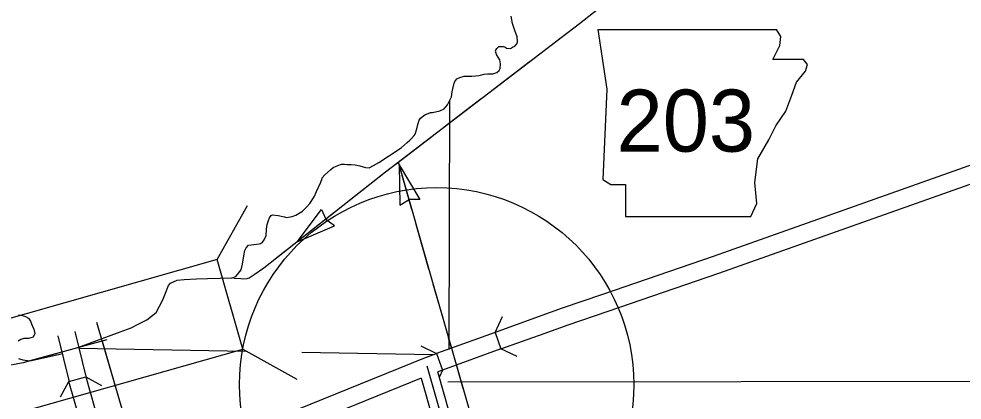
# Model space of a CAD drawing. Extents: x 1373094 to 1376427, y 1168361 to 1170494.
# Drawn here: x 1373442.4 to 1373576.1, y 1170261.2 to 1170315.3 of the extents above; entities that cross this region are included whole.
import ezdxf

# ---------------------------------------------------------------- set-up
doc = ezdxf.new("R2010")
doc.units = 0
doc.layers.add('R_Axis', color=7, linetype='Continuous')
doc.layers.add('R_Draft', color=7, linetype='Continuous')

msp = doc.modelspace()

# ---------------------------------------------------------------- linework, layer by layer
at = {"layer": 'R_Axis'}
for p, q in [((1373524.43, 1170313.73), (1373525.7, 1170305.27)), ((1373550.37, 1170312.74), (1373549.78, 1170313.72)), ((1373550.23, 1170311.47), (1373550.37, 1170312.74)), ((1373549.24, 1170309.5), (1373550.23, 1170311.47)), ((1373553.61, 1170309.5), (1373549.24, 1170309.5)), ((1373554.17, 1170308.79), (1373553.61, 1170309.5)), ((1373552.62, 1170306.26), (1373553.89, 1170307.81)), ((1373553.89, 1170307.81), (1373554.17, 1170308.79)), ((1373551.92, 1170304.42), (1373552.62, 1170306.26)), ((1373525.7, 1170305.27), (1373525.13, 1170292.44)), ((1373551.07, 1170302.17), (1373551.92, 1170304.42)), ((1373549.66, 1170300.05), (1373551.07, 1170302.17)), ((1373548.68, 1170298.08), (1373549.66, 1170300.05)), ((1373547.13, 1170295.4), (1373548.68, 1170298.08)), ((1373496.29, 1170294.55), (1373496.37, 1170288.83)), ((1373496.29, 1170294.55), (1373499.22, 1170289.64)), ((1373546.7, 1170292.02), (1373547.13, 1170295.4)), ((1373525.13, 1170292.44), (1373526.26, 1170291.74)), ((1373526.26, 1170291.74), (1373528.37, 1170291.74)), ((1373528.37, 1170291.74), (1373528.37, 1170287.22)), ((1373546.98, 1170289.06), (1373546.7, 1170292.02)), ((1373496.37, 1170288.83), (1373497.68, 1170289.61)), ((1373499.22, 1170289.64), (1373497.7, 1170289.62)), ((1373546.14, 1170287.22), (1373546.98, 1170289.06)), ((1373470.5, 1170281.1), (1373474.79, 1170288.78)), ((1373481.84, 1170283.63), (1373485.26, 1170288.21)), ((1373485.26, 1170288.21), (1373485.86, 1170286.82)), ((1373487.09, 1170285.89), (1373485.87, 1170286.8)), ((1373528.37, 1170287.22), (1373546.14, 1170287.22)), ((1373481.84, 1170283.63), (1373487.09, 1170285.89)), ((1373474.1, 1170268.4), (1373481.79, 1170264.11)), ((1373501.59, 1170267.78), (1373502.44, 1170265.43))]:
    msp.add_line(p, q, dxfattribs=at)
for points in [[(1373569.11, 1170326.38), (1373530.8, 1170320.46), (1373530.35, 1170320.31), (1373529.83, 1170320.03), (1373529.18, 1170319.74), (1373527.99, 1170319.08), (1373525.82, 1170317.65), (1373521.83, 1170314.55), (1373494.34, 1170293.49), (1373477.11, 1170279.9), (1373475.7, 1170278.91), (1373475.01, 1170278.46), (1373474.69, 1170278.37), (1373474.24, 1170278.33), (1373473.82, 1170278.35), (1373472.85, 1170278.41)], [(1373493.37, 1170294.86), (1373496.58, 1170296.95), (1373497.41, 1170297.69), (1373497.81, 1170298.06), (1373498.04, 1170298.29), (1373498.4, 1170298.7), (1373498.53, 1170298.87), (1373498.79, 1170299.63), (1373498.92, 1170300.27), (1373499.12, 1170300.87), (1373499.31, 1170301.14), (1373499.91, 1170301.64), (1373500.74, 1170301.95), (1373501, 1170301.95), (1373502.03, 1170302.19), (1373502.66, 1170302.49), (1373503.12, 1170303.06), (1373503.68, 1170304.2), (1373503.81, 1170304.9), (1373504.07, 1170306.11), (1373504.16, 1170306.37), (1373504.46, 1170306.74), (1373504.86, 1170306.95), (1373505.49, 1170307.12), (1373505.82, 1170307.12), (1373506.15, 1170307.12), (1373506.59, 1170307.12), (1373507.08, 1170307.16), (1373507.62, 1170307.23), (1373508.31, 1170307.4), (1373508.81, 1170307.47), (1373509.57, 1170307.44), (1373510.11, 1170307.64), (1373510.44, 1170307.91), (1373510.57, 1170308.21), (1373510.66, 1170308.85), (1373510.53, 1170309.45), (1373510.29, 1170309.81), (1373510.05, 1170310.18), (1373510.02, 1170310.41), (1373509.95, 1170310.58), (1373509.99, 1170310.68), (1373509.95, 1170310.81), (1373510.02, 1170310.91), (1373510.12, 1170311.05), (1373510.41, 1170311.32), (1373510.74, 1170311.35), (1373511.08, 1170311.35), (1373511.24, 1170311.26), (1373511.51, 1170311.09), (1373512.04, 1170311.06), (1373512.34, 1170311.23), (1373512.67, 1170311.36), (1373513, 1170311.73), (1373513.03, 1170311.97), (1373513, 1170312.7), (1373512.69, 1170313.6), (1373512.32, 1170314.6), (1373512.15, 1170315.63)], [(1373493.37, 1170294.86), (1373496.58, 1170296.95), (1373497.41, 1170297.69), (1373497.81, 1170298.06), (1373498.04, 1170298.29), (1373498.4, 1170298.7), (1373498.53, 1170298.87), (1373498.79, 1170299.63), (1373498.92, 1170300.27), (1373499.12, 1170300.87), (1373499.31, 1170301.14), (1373499.91, 1170301.64), (1373500.74, 1170301.95), (1373501, 1170301.95), (1373502.03, 1170302.19), (1373502.66, 1170302.49), (1373503.12, 1170303.06), (1373503.68, 1170304.2), (1373503.81, 1170304.9), (1373504.07, 1170306.11), (1373504.16, 1170306.37), (1373504.46, 1170306.74), (1373504.86, 1170306.95), (1373505.49, 1170307.12), (1373505.82, 1170307.12), (1373506.15, 1170307.12), (1373506.59, 1170307.12), (1373507.08, 1170307.16), (1373507.62, 1170307.23), (1373508.31, 1170307.4), (1373508.81, 1170307.47), (1373509.57, 1170307.44), (1373510.11, 1170307.64), (1373510.44, 1170307.91), (1373510.57, 1170308.21), (1373510.66, 1170308.85), (1373510.53, 1170309.45), (1373510.29, 1170309.81), (1373510.05, 1170310.18), (1373510.02, 1170310.41), (1373509.95, 1170310.58), (1373509.99, 1170310.68), (1373509.95, 1170310.81), (1373510.02, 1170310.91), (1373510.12, 1170311.05), (1373510.41, 1170311.32), (1373510.74, 1170311.35), (1373511.08, 1170311.35), (1373511.24, 1170311.26), (1373511.51, 1170311.09), (1373512.04, 1170311.06), (1373512.34, 1170311.23), (1373512.67, 1170311.36), (1373513, 1170311.73), (1373513.03, 1170311.97), (1373513, 1170312.7), (1373512.69, 1170313.6), (1373512.32, 1170314.6), (1373512.15, 1170315.63)], [(1373521.87, 1170314.58), (1373521.83, 1170314.55), (1373519.25, 1170312.57)], [(1373524.43, 1170313.73), (1373549.78, 1170313.72)], [(1373519.25, 1170312.57), (1373516.63, 1170310.56)], [(1373514.89, 1170309.23), (1373509.64, 1170305.21)], [(1373610.11, 1170305.99), (1373590.89, 1170299.44), (1373582.99, 1170296.51), (1373575.57, 1170293.87), (1373540.78, 1170281.53), (1373525.11, 1170276.16), (1373519.4, 1170274.18), (1373516, 1170272.99), (1373509.86, 1170270.77)], [(1373507.9, 1170303.88), (1373502.66, 1170299.86)], [(1373503.4, 1170303.62), (1373503.31, 1170268.34)], [(1373510.71, 1170268.42), (1373516.84, 1170270.63), (1373520.22, 1170271.82), (1373525.92, 1170273.79), (1373541.61, 1170279.17), (1373576.41, 1170291.52), (1373583.85, 1170294.16), (1373591.72, 1170297.08), (1373607.57, 1170302.48)], [(1373500.91, 1170298.53), (1373495.67, 1170294.51)], [(1373484.23, 1170290), (1373484.56, 1170290.77), (1373485.15, 1170292.08), (1373485.35, 1170292.58), (1373485.35, 1170292.68), (1373485.74, 1170293.12), (1373486.57, 1170293.89), (1373486.93, 1170294.16), (1373487.56, 1170294.46), (1373488.12, 1170294.63), (1373488.52, 1170294.63), (1373488.92, 1170294.6), (1373489.49, 1170294.57), (1373490.02, 1170294.54), (1373490.72, 1170294.41), (1373491.48, 1170294.15), (1373492.02, 1170294.09), (1373492.65, 1170294.43), (1373493.37, 1170294.86)], [(1373484.23, 1170290), (1373484.56, 1170290.77), (1373485.15, 1170292.08), (1373485.35, 1170292.58), (1373485.35, 1170292.68), (1373485.74, 1170293.12), (1373486.57, 1170293.89), (1373486.93, 1170294.16), (1373487.56, 1170294.46), (1373488.12, 1170294.63), (1373488.52, 1170294.63), (1373488.92, 1170294.6), (1373489.49, 1170294.57), (1373490.02, 1170294.54), (1373490.72, 1170294.41), (1373491.48, 1170294.15), (1373492.02, 1170294.09), (1373492.65, 1170294.43), (1373493.37, 1170294.86)], [(1373524.23, 1170198.47), (1373524.1, 1170198.69), (1373523.51, 1170200.1), (1373522.35, 1170203.74), (1373521.65, 1170205.8), (1373520.91, 1170207.92), (1373520.55, 1170209.9), (1373519.39, 1170214.19), (1373515, 1170229.71), (1373510.38, 1170245.3), (1373501.03, 1170277.83), (1373496.18, 1170294.91)], [(1373498.09, 1170288.2), (1373496.29, 1170294.55)], [(1373493.93, 1170293.17), (1373488.75, 1170289.08)], [(1373450.88, 1170268.69), (1373456.74, 1170270.85), (1373458.27, 1170271.4), (1373459.36, 1170271.97), (1373460.52, 1170272.54), (1373461.81, 1170273.59), (1373462.79, 1170275.39), (1373463.06, 1170276.1), (1373463.58, 1170277.43), (1373463.88, 1170277.74), (1373464.8, 1170278.18), (1373465.8, 1170278.28), (1373467.53, 1170278.36), (1373469.12, 1170278.4), (1373470.92, 1170278.48), (1373472.58, 1170278.52), (1373473.11, 1170278.69), (1373473.87, 1170279.63), (1373474.06, 1170280.43), (1373474.25, 1170281.64), (1373474.41, 1170282.37), (1373474.58, 1170282.77), (1373474.94, 1170283.14), (1373476.43, 1170283.32), (1373476.63, 1170283.38), (1373476.9, 1170283.59), (1373477.16, 1170283.92), (1373477.42, 1170284.52), (1373477.48, 1170285.39), (1373477.55, 1170286.09), (1373477.74, 1170286.66), (1373477.91, 1170287), (1373478.14, 1170287.37), (1373478.33, 1170287.43), (1373479.1, 1170287.34), (1373480.03, 1170287.14), (1373480.3, 1170287.08), (1373481.09, 1170287.22), (1373481.63, 1170287.39), (1373482.59, 1170287.96), (1373483.21, 1170288.6), (1373483.61, 1170289.03), (1373484.23, 1170290)], [(1373472.52, 1170278.52), (1373472.58, 1170278.52), (1373473.11, 1170278.69), (1373473.87, 1170279.63), (1373474.06, 1170280.43), (1373474.25, 1170281.64), (1373474.41, 1170282.37), (1373474.58, 1170282.77), (1373474.94, 1170283.14), (1373476.43, 1170283.32), (1373476.63, 1170283.38), (1373476.9, 1170283.59), (1373477.16, 1170283.92), (1373477.42, 1170284.52), (1373477.48, 1170285.39), (1373477.55, 1170286.09), (1373477.74, 1170286.66), (1373477.91, 1170287), (1373478.14, 1170287.37), (1373478.33, 1170287.43), (1373479.1, 1170287.34), (1373480.03, 1170287.14), (1373480.3, 1170287.08), (1373481.09, 1170287.22), (1373481.63, 1170287.39), (1373482.59, 1170287.96), (1373483.21, 1170288.6), (1373483.61, 1170289.03), (1373484.23, 1170290)], [(1373487.02, 1170287.72), (1373481.84, 1170283.63)], [(1373500.49, 1170279.74), (1373498.69, 1170286.09)], [(1373480.11, 1170282.27), (1373477.52, 1170280.22)], [(1373477.52, 1170280.22), (1373477.11, 1170279.9), (1373475.7, 1170278.91), (1373475.01, 1170278.46), (1373474.79, 1170278.4)], [(1373502.49, 1170272.77), (1373501.09, 1170277.62)], [(1373442.3, 1170273.24), (1373442.9, 1170273.14), (1373443.3, 1170273.01), (1373443.74, 1170272.78), (1373444, 1170272.38), (1373444.27, 1170271.75), (1373444.51, 1170271.22), (1373444.65, 1170270.62), (1373444.38, 1170270.11), (1373443.72, 1170269.88), (1373443.06, 1170269.91), (1373442.66, 1170269.74), (1373442.26, 1170269.53)], [(1373509.86, 1170270.77), (1373510.93, 1170273.04)], [(1373453.37, 1170272.22), (1373456.95, 1170259.94), (1373461.88, 1170242.54)], [(1373447.88, 1170270.27), (1373449.48, 1170263.75)], [(1373450.31, 1170270.89), (1373451.87, 1170264.5)], [(1373509.86, 1170270.77), (1373501.59, 1170267.78)], [(1373509.86, 1170270.77), (1373510.71, 1170268.42)], [(1373454.84, 1170269.71), (1373443.91, 1170266.71)], [(1373454.16, 1170269.52), (1373456.95, 1170259.94), (1373464.6, 1170232.93), (1373467.31, 1170223.27), (1373477.47, 1170186.82), (1373483.75, 1170164.69), (1373489.97, 1170143.28), (1373494.03, 1170129.36), (1373496.54, 1170120.87)], [(1373499.33, 1170268.85), (1373501.59, 1170267.78)], [(1373503.7, 1170268.55), (1373503.29, 1170269.98)], [(1373442.31, 1170267.06), (1373442.48, 1170267), (1373442.91, 1170266.87), (1373443.94, 1170266.71), (1373448.41, 1170267.73)], [(1373447.64, 1170267.73), (1373443.91, 1170266.71), (1373443.17, 1170266.51)], [(1373450.88, 1170268.54), (1373474.58, 1170268.12)], [(1373474.25, 1170256.62), (1373475.46, 1170257.24), (1373476.58, 1170257.71), (1373499.78, 1170267.13), (1373501.59, 1170267.78)], [(1373482.48, 1170267.98), (1373501.07, 1170267.65)], [(1373510.71, 1170268.42), (1373502.44, 1170265.43)], [(1373512.98, 1170267.36), (1373510.71, 1170268.42)], [(1373442.99, 1170266.46), (1373429.04, 1170263.82)], [(1373443.91, 1170266.71), (1373442.99, 1170266.46)], [(1373505.34, 1170262.82), (1373504.39, 1170266.14)], [(1373514.35, 1170216.5), (1373511.73, 1170226.02), (1373504.38, 1170251.41), (1373500.24, 1170265.97)], [(1373502.44, 1170265.43), (1373501.76, 1170265.19)], [(1373503.48, 1170259.15), (1373501.76, 1170265.19)], [(1373502.44, 1170265.43), (1373501.97, 1170264.44)], [(1373448.25, 1170261.6), (1373449.47, 1170263.78)], [(1373449.47, 1170263.78), (1373451.87, 1170264.47)], [(1373455.72, 1170241.82), (1373454.41, 1170246.5), (1373451.94, 1170255.09), (1373449.47, 1170263.78)], [(1373451.87, 1170264.47), (1373454.06, 1170263.25)], [(1373451.87, 1170264.47), (1373454.34, 1170255.78), (1373456.82, 1170247.18), (1373457.84, 1170243.55)], [(1373499.41, 1170264.28), (1373477.54, 1170255.4), (1373476.5, 1170254.97), (1373475.66, 1170254.54)], [(1373499.41, 1170264.28), (1373501.07, 1170258.46)], [(1373503.19, 1170263.74), (1373586.28, 1170263.85), (1373609.43, 1170263.26)]]:
    msp.add_lwpolyline(points, dxfattribs=at)
msp.add_lwpolyline([(1373436.01, 1170257.59), (1373474.1, 1170268.4), (1373470.5, 1170281.1), (1373432.41, 1170270.29)], close=True, dxfattribs=at)
at = {"layer": 'R_Draft'}
msp.add_circle((1373501.59, 1170263.37), 27.94, dxfattribs=at)

# ---------------------------------------------------------------- texts
at = {"layer": 'R_Axis'}
msp.add_text('203', height=8.8, dxfattribs=at).set_placement((1373527.09, 1170296.41))

doc.saveas('drawing.dxf')
